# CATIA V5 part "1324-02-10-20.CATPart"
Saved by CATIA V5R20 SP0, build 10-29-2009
Part number: 1324-02-10-20
Revision: ANY
Definition: UNKNOWN
Nomenclature: 1324-02-10-20
Source: Unknown
Bounding box of the stored display mesh (mm): x -8.75 to 8.75, y 0 to 3, z -8.75 to 8.75
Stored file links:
  C:\Users\Utente\Desktop\IO LAVORO\3D X SITO CF\CUMSA\3D files SL.602008\SL 602008\1324-02-10-20.CATPart
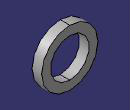
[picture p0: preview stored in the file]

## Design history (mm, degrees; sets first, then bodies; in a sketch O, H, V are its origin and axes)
Body1 "Saliente-Extruir1" (main body)
  Solid1: solid without history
